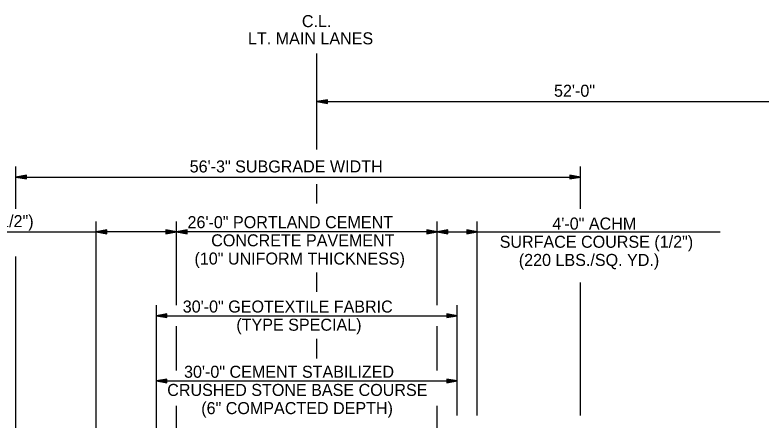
# Model space of a CAD drawing. Extents: x 1734743 to 1735935, y 759845 to 763831.
# Drawn here: x 1735671 to 1735745.4, y 760877.4 to 760917.8 of the extents above; entities that cross this region are included whole.
import ezdxf

# ---------------------------------------------------------------- set-up
doc = ezdxf.new("R2010")
doc.units = 0
doc.layers.add('19', color=7, linetype='Continuous')

msp = doc.modelspace()

# ---------------------------------------------------------------- linework, layer by layer
at = {"layer": '19'}
for p, q in [((1735701.144, 760904.381), (1735701.144, 760913.944)), ((1735702.194, 760909.346), (1735701.144, 760909.163)), ((1735701.144, 760909.163), (1735753.144, 760909.163)), ((1735701.144, 760909.163), (1735702.194, 760908.979)), ((1735702.194, 760909.25), (1735701.424, 760909.189)), ((1735701.424, 760909.136), (1735702.194, 760909.066)), ((1735702.194, 760908.979), (1735702.194, 760909.346)), ((1735671.142, 760898.458), (1735671.142, 760902.679)), ((1735727.419, 760898.458), (1735727.419, 760902.679)), ((1735672.192, 760901.816), (1735671.142, 760901.633)), ((1735671.142, 760901.633), (1735727.419, 760901.633)), ((1735671.142, 760901.633), (1735672.192, 760901.449)), ((1735672.192, 760901.72), (1735671.422, 760901.659)), ((1735671.422, 760901.606), (1735672.192, 760901.536)), ((1735672.192, 760901.449), (1735672.192, 760901.816)), ((1735726.369, 760901.817), (1735726.369, 760901.449)), ((1735727.419, 760901.633), (1735726.369, 760901.817)), ((1735727.139, 760901.659), (1735726.369, 760901.72)), ((1735726.369, 760901.449), (1735727.419, 760901.633)), ((1735726.369, 760901.537), (1735727.139, 760901.607)), ((1735701.144, 760898.997), (1735701.144, 760900.929)), ((1735679.144, 760891.537), (1735679.144, 760897.217)), ((1735687.144, 760888.858), (1735687.144, 760897.216)), ((1735713.144, 760888.858), (1735713.144, 760897.216)), ((1735717.141, 760877.85), (1735717.141, 760897.213)), ((1735680.194, 760896.355), (1735679.144, 760896.171)), ((1735680.194, 760896.258), (1735679.424, 760896.197)), ((1735680.194, 760895.987), (1735680.194, 760896.355)), ((1735686.094, 760896.355), (1735686.094, 760895.987)), ((1735687.144, 760896.171), (1735686.094, 760896.355)), ((1735686.864, 760896.197), (1735686.094, 760896.258)), ((1735688.194, 760896.355), (1735687.144, 760896.171)), ((1735688.194, 760896.258), (1735687.424, 760896.197)), ((1735688.194, 760895.987), (1735688.194, 760896.355)), ((1735712.094, 760896.355), (1735712.094, 760895.987)), ((1735713.144, 760896.171), (1735712.094, 760896.355)), ((1735712.864, 760896.197), (1735712.094, 760896.258)), ((1735714.194, 760896.355), (1735713.144, 760896.171)), ((1735714.194, 760896.258), (1735713.424, 760896.197)), ((1735714.194, 760895.987), (1735714.194, 760896.355)), ((1735716.091, 760896.355), (1735716.091, 760895.987)), ((1735717.141, 760896.171), (1735716.091, 760896.355)), ((1735716.861, 760896.197), (1735716.091, 760896.258)), ((1735643.287, 760896.171), (1735679.144, 760896.171)), ((1735687.144, 760896.171), (1735679.144, 760896.171)), ((1735679.144, 760896.171), (1735680.194, 760895.987)), ((1735679.424, 760896.145), (1735680.194, 760896.075)), ((1735686.094, 760895.987), (1735687.144, 760896.171)), ((1735686.094, 760896.075), (1735686.864, 760896.145)), ((1735687.144, 760896.171), (1735688.194, 760895.987)), ((1735713.144, 760896.171), (1735687.144, 760896.171)), ((1735687.424, 760896.145), (1735688.194, 760896.075)), ((1735712.094, 760895.987), (1735713.144, 760896.171)), ((1735712.094, 760896.075), (1735712.864, 760896.145)), ((1735713.144, 760896.171), (1735717.141, 760896.171)), ((1735713.144, 760896.171), (1735714.194, 760895.987)), ((1735713.424, 760896.145), (1735714.194, 760896.075)), ((1735716.091, 760895.987), (1735717.141, 760896.171)), ((1735716.091, 760896.075), (1735716.861, 760896.145)), ((1735717.141, 760896.171), (1735741.351, 760896.171)), ((1735671.142, 760866.731), (1735671.142, 760893.709)), ((1735701.144, 760890.176), (1735701.144, 760892.108)), ((1735679.144, 760866.731), (1735679.144, 760891.537)), ((1735727.419, 760877.85), (1735727.419, 760891.118)), ((1735685.145, 760867.874), (1735685.145, 760888.858)), ((1735715.144, 760877.85), (1735715.144, 760888.858)), ((1735686.195, 760887.995), (1735685.145, 760887.812)), ((1735685.145, 760887.812), (1735686.195, 760887.628)), ((1735685.145, 760887.812), (1735715.144, 760887.812)), ((1735686.195, 760887.899), (1735685.425, 760887.838)), ((1735685.425, 760887.785), (1735686.195, 760887.715)), ((1735686.195, 760887.628), (1735686.195, 760887.995)), ((1735714.094, 760887.995), (1735714.094, 760887.628)), ((1735715.144, 760887.812), (1735714.094, 760887.995)), ((1735714.864, 760887.838), (1735714.094, 760887.899)), ((1735714.094, 760887.628), (1735715.144, 760887.812)), ((1735714.094, 760887.715), (1735714.864, 760887.785)), ((1735687.144, 760882.356), (1735687.144, 760886.766)), ((1735713.144, 760882.356), (1735713.144, 760886.766)), ((1735701.144, 760883.558), (1735701.144, 760885.49)), ((1735685.145, 760876.615), (1735685.145, 760882.356)), ((1735686.195, 760881.493), (1735685.145, 760881.31)), ((1735686.195, 760881.397), (1735685.425, 760881.336)), ((1735686.195, 760881.126), (1735686.195, 760881.493)), ((1735714.094, 760881.493), (1735714.094, 760881.126)), ((1735715.144, 760881.31), (1735714.094, 760881.493)), ((1735714.864, 760881.336), (1735714.094, 760881.397)), ((1735685.145, 760881.31), (1735686.195, 760881.126)), ((1735685.145, 760881.31), (1735715.144, 760881.31)), ((1735685.425, 760881.283), (1735686.195, 760881.213)), ((1735714.094, 760881.126), (1735715.144, 760881.31)), ((1735714.094, 760881.213), (1735714.864, 760881.283)), ((1735687.144, 760867.874), (1735687.144, 760878.838)), ((1735713.144, 760877.958), (1735713.144, 760878.838)), ((1735713.144, 760855.111), (1735713.144, 760877.958))]:
    msp.add_line(p, q, dxfattribs=at)

# ---------------------------------------------------------------- texts
for s, p in [('C.L.', (1735699.651, 760916.577)), ('LT. MAIN LANES', (1735694.275, 760914.861)), ('52\'-0"', (1735724.791, 760909.639)), ('56\'-3" SUBGRADE WIDTH', (1735688.462, 760902.091)), ('8\'-0" ACHM SURFACE COURSE (1/2")', (1735644.792, 760896.638)), ('26\'-0" PORTLAND CEMENT', (1735688.245, 760896.535)), ('4\'-0" ACHM ', (1735724.624, 760896.393)), ('CONCRETE PAVEMENT', (1735690.607, 760894.723)), ('SURFACE COURSE (1/2")', (1735719.371, 760894.58)), ('(10" UNIFORM THICKNESS)', (1735688.94, 760892.91)), ('(220 LBS./SQ. YD.)', (1735721.279, 760892.768)), ('30\'-0" GEOTEXTILE FABRIC', (1735687.77, 760888.123)), ('(TYPE SPECIAL)', (1735693.113, 760886.311)), ('30\'-0" CEMENT STABILIZED ', (1735687.899, 760881.621)), ('CRUSHED STONE BASE COURSE', (1735686.222, 760879.809)), ('(6" COMPACTED DEPTH)', (1735689.614, 760877.996))]:
    msp.add_text(s, height=1.2, dxfattribs=at).set_placement(p)

doc.saveas('drawing.dxf')
